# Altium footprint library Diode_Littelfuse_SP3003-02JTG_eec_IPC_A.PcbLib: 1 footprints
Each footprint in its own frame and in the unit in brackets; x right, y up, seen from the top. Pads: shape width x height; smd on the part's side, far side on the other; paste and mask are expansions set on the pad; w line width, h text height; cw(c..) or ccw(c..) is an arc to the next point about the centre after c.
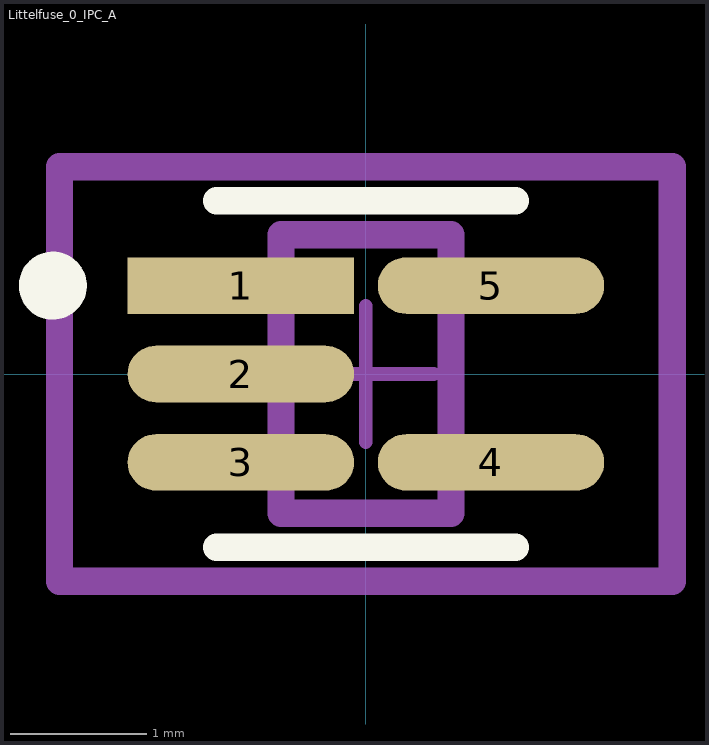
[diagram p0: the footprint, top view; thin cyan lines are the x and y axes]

## Littelfuse_0_IPC_A [mm]
pads (5):
  rect 1.666x0.416 smd paste+0 mask+0: 1(-0.92,0.65)
  rrect100% 1.666x0.416 smd paste+0 mask+0: 2(-0.92,0) 3(-0.92,-0.65) 4(0.92,-0.65) 5(0.92,0.65)
Top Overlay:
  circle w0.25: c-2.303,0.65 r0.125
  lines w0.2: -1.1,-1.275 1.1,-1.275 ; -1.1,1.275 1.1,1.275
Mechanical 10:
  lines w0.2: -2.253,-1.525 2.253,-1.525 2.253,1.525 -2.253,1.525 -2.253,-1.525
  text ".Designator" at 0,0 h1
Mechanical 12:
  lines w0.2: -0.625,-1.025 0.625,-1.025 0.625,1.025 -0.625,1.025 -0.625,-1.025
Mechanical 15:
  lines w0.1: -0.5,0 0.5,0 ; 0,-0.5 0,0.5
  lines w0.2: -2.253,-1.525 2.253,-1.525 2.253,1.525 -2.253,1.525 -2.253,-1.525
3D body "Diode_Littelfuse_SP3003-02JTG_eec.STEP": height 0.25, standoff 0, extent -2.253,-1.525 2.253,1.525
